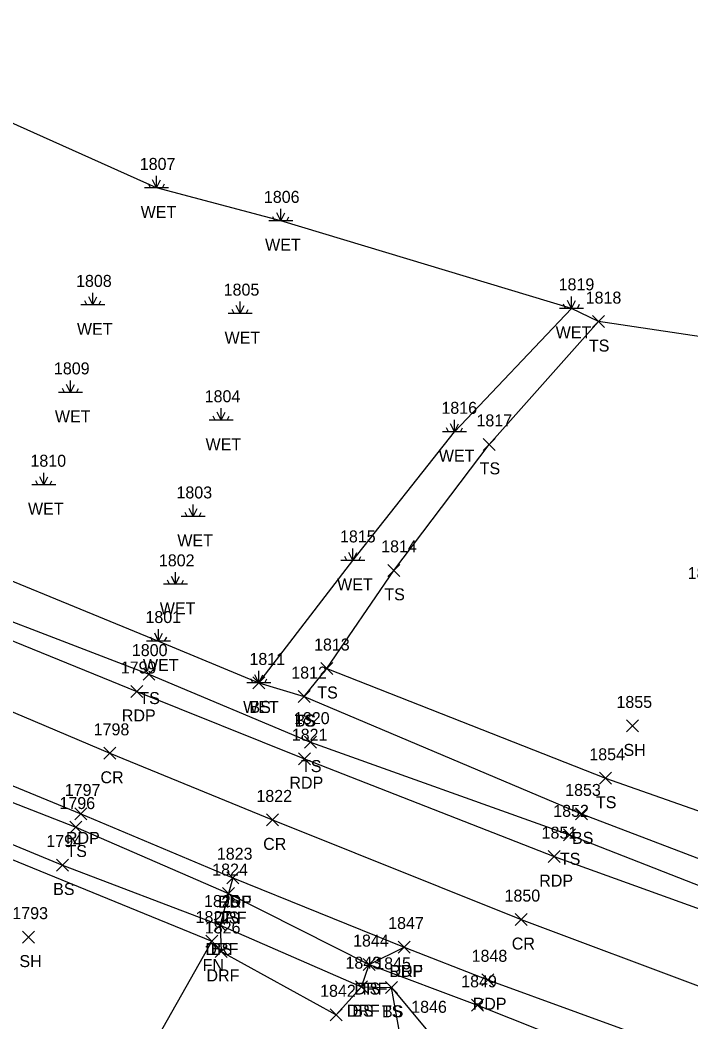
# Model space of a CAD drawing. Extents: x 1459992 to 1461532, y 647785 to 648535.
# Drawn here: x 1461005.9 to 1461117.9, y 648288.6 to 648455.8 of the extents above; entities that cross this region are included whole.
import ezdxf

# ---------------------------------------------------------------- set-up
doc = ezdxf.new("R2010")
doc.units = 0
for name, color, linetype in [('L_A', 7, 'Continuous'), ('L_I', 7, 'Continuous'), ('L_TIC', 7, 'Continuous'), ('LELB', 7, 'Continuous'), ('LFNC', 7, 'Continuous'), ('LSOGP', 7, 'Continuous'), ('LWET', 7, 'Continuous'), ('P_A', 7, 'Continuous'), ('P_I', 7, 'Continuous'), ('P_TIC', 7, 'Continuous'), ('PET', 7, 'Continuous'), ('PRC', 7, 'Continuous'), ('R_A', 7, 'Continuous'), ('R_I', 7, 'Continuous'), ('R_TIC', 7, 'Continuous'), ('RDF', 7, 'Continuous')]:
    doc.layers.add(name, color=color, linetype=linetype)

msp = doc.modelspace()

# ---------------------------------------------------------------- linework, layer by layer
at = {"layer": 'L_TIC'}
for points in [[(1461101.42, 648404.45), (1461103.42, 648406.45)], [(1461103.42, 648404.45), (1461101.42, 648406.45)], [(1461083.2, 648383.96), (1461085.2, 648385.96)], [(1461085.2, 648383.96), (1461083.2, 648385.96)], [(1461067.29, 648362.94), (1461069.29, 648364.94)], [(1461069.29, 648362.94), (1461067.29, 648364.94)], [(1461056.1, 648346.56), (1461058.1, 648348.56)], [(1461058.1, 648346.56), (1461056.1, 648348.56)], [(1461056.1, 648346.56), (1461058.1, 648348.56)], [(1461058.1, 648346.56), (1461056.1, 648348.56)], [(1461026.43, 648345.63), (1461028.43, 648347.63)], [(1461028.43, 648345.63), (1461026.43, 648347.63)], [(1461044.75, 648344.16), (1461046.75, 648346.16)], [(1461046.75, 648344.16), (1461044.75, 648346.16)], [(1461052.3, 648341.88), (1461054.3, 648343.88)], [(1461054.3, 648341.88), (1461052.3, 648343.88)], [(1461052.3, 648341.88), (1461054.3, 648343.88)], [(1461054.3, 648341.88), (1461052.3, 648343.88)], [(1461107.11, 648336.98), (1461109.11, 648338.98)], [(1461109.11, 648336.98), (1461107.11, 648338.98)], [(1461053.39, 648334.28), (1461055.39, 648336.28)], [(1461055.39, 648334.28), (1461053.39, 648336.28)], [(1461102.6, 648328.25), (1461104.6, 648330.25)], [(1461104.6, 648328.25), (1461102.6, 648330.25)], [(1461098.57, 648322.3), (1461100.57, 648324.3)], [(1461100.57, 648322.3), (1461098.57, 648324.3)], [(1461014.24, 648320.11), (1461016.24, 648322.11)], [(1461016.24, 648320.11), (1461014.24, 648322.11)], [(1461096.58, 648318.81), (1461098.58, 648320.81)], [(1461098.58, 648318.81), (1461096.58, 648320.81)], [(1461012, 648313.77), (1461014, 648315.77)], [(1461014, 648313.77), (1461012, 648315.77)], [(1461039.67, 648309.01), (1461041.67, 648311.01)], [(1461041.67, 648309.01), (1461039.67, 648311.01)], [(1461038.31, 648303.76), (1461040.31, 648305.76)], [(1461040.31, 648303.76), (1461038.31, 648305.76)], [(1461006.32, 648301.74), (1461008.32, 648303.74)], [(1461008.32, 648301.74), (1461006.32, 648303.74)], [(1461036.89, 648301.09), (1461038.89, 648303.09)], [(1461038.89, 648301.09), (1461036.89, 648303.09)], [(1461063.18, 648297.16), (1461065.18, 648299.16)], [(1461065.18, 648297.16), (1461063.18, 648299.16)], [(1461061.9, 648293.47), (1461063.9, 648295.47)], [(1461063.9, 648293.47), (1461061.9, 648295.47)], [(1461066.87, 648293.36), (1461068.87, 648295.36)], [(1461068.87, 648293.36), (1461066.87, 648295.36)], [(1461066.87, 648293.36), (1461068.87, 648295.36)], [(1461068.87, 648293.36), (1461066.87, 648295.36)], [(1461081.22, 648290.36), (1461083.22, 648292.36)], [(1461083.22, 648290.36), (1461081.22, 648292.36)]]:
    msp.add_lwpolyline(points, dxfattribs=at)
at = {"layer": 'LELB'}
for points in [[(1461053.3, 648342.88), (1461057.1, 648347.56), (1461103.6, 648329.25), (1461132.09, 648319.28), (1461156.26, 648311.83), (1461179.8, 648313.29), (1461203.15, 648318.77), (1461223.06, 648334.41), (1461252.96, 648329.42), (1461275.76, 648346.01), (1461293.92, 648360.57), (1461297.9, 648376.52), (1461309.92, 648382.32), (1461323.28, 648384.14), (1461344.65, 648406.6), (1461362.09, 648421.03), (1461389.72, 648443.02), (1461411.96, 648455.77)], [(1461045.75, 648345.16), (1461053.3, 648342.88), (1461099.57, 648323.3), (1461128.93, 648312.14), (1461154.02, 648304.18), (1461179.99, 648301.37), (1461204.48, 648303), (1461231.37, 648312.49), (1461255.41, 648321.87), (1461278.91, 648340.15), (1461298.64, 648355.28), (1461307.84, 648362.71), (1461328.64, 648380.09), (1461350.69, 648401.06), (1461366.77, 648414.15), (1461392.6, 648435.99), (1461415.7, 648449.6)], [(1460952.34, 648377.13), (1460985.69, 648362.66), (1461027.43, 648346.63), (1461054.39, 648335.28), (1461097.58, 648319.81), (1461127.3, 648308.18), (1461153.51, 648301.33), (1461179.78, 648297.83), (1461204.84, 648300.47), (1461233.15, 648308.09), (1461257.01, 648318.59), (1461281.51, 648336.52), (1461300.79, 648352.57), (1461310.07, 648360.68), (1461331.77, 648379.2), (1461352.47, 648399.38), (1461367.35, 648413.21), (1461394.44, 648433.89), (1461417.38, 648445.8)], [(1461057.1, 648347.56), (1461068.29, 648363.94), (1461084.2, 648384.96), (1461102.42, 648405.45)], [(1460941.15, 648349.78), (1460973.92, 648337.2), (1461015.24, 648321.11), (1461040.67, 648310.01), (1461064.18, 648298.16), (1461082.22, 648291.36), (1461125.02, 648274.34), (1461150.75, 648265.39), (1461172.28, 648256.95), (1461198.57, 648246.42), (1461223, 648236.28), (1461241.79, 648231.37), (1461257.62, 648226.89), (1461266.9, 648221.63), (1461276.01, 648214.68), (1461281.47, 648211.06), (1461286.34, 648210.46)], [(1460939.64, 648344.38), (1460971.19, 648332.05), (1461013, 648314.77), (1461039.31, 648304.76), (1461062.9, 648294.47), (1461067.87, 648294.36), (1461073.92, 648287.11), (1461122.33, 648270.19), (1461146.57, 648259.51), (1461168.44, 648252.02), (1461196.41, 648241.56), (1461220.18, 648231.28), (1461239.03, 648226.47), (1461251, 648216.36), (1461259.3, 648208.22), (1461262.9, 648204.94)], [(1461027.01, 648215.7), (1461045.55, 648230.6), (1461059.33, 648245.65), (1461068.32, 648268.11), (1461070.7, 648278.87), (1461067.87, 648294.36)]]:
    msp.add_lwpolyline(points, dxfattribs=at)
at = {"layer": 'LFNC'}
msp.add_lwpolyline([(1460991.77, 648320.92), (1461037.89, 648302.09), (1461026.11, 648281.23)], dxfattribs=at)
at = {"layer": 'LSOGP'}
msp.add_lwpolyline([(1461138.91, 648400.04), (1461102.42, 648405.45), (1461097.92, 648407.66), (1461049.42, 648422.26), (1461028.66, 648427.76), (1461000.6, 648440.35), (1460993.65, 648440.24), (1460983.9, 648441.23), (1460975.78, 648424.57), (1460965.77, 648408.07), (1460958.96, 648389.21), (1460957.54, 648386.1), (1460955.38, 648382.22), (1460952.34, 648377.13), (1460950.93, 648374.58), (1460946.83, 648364.55), (1460942.85, 648353.98), (1460941.15, 648349.78), (1460940.52, 648347.48), (1460939.64, 648344.38), (1460937.03, 648338.08), (1460933.59, 648326.77), (1460928.43, 648303.96), (1460921.84, 648282.44)], dxfattribs=at)
at = {"layer": 'LWET'}
for p, q in [((1461028.66, 648427.76), (1461028.66, 648429.76)), ((1461027.66, 648427.76), (1461027.33, 648428.43)), ((1461028.66, 648427.76), (1461028, 648429.1)), ((1461028.66, 648427.76), (1461029.33, 648429.1)), ((1461029.66, 648427.76), (1461030, 648428.43)), ((1461030.66, 648427.76), (1461026.66, 648427.76)), ((1461048.42, 648422.26), (1461048.09, 648422.93)), ((1461049.42, 648422.26), (1461048.76, 648423.6)), ((1461049.42, 648422.26), (1461049.42, 648424.26)), ((1461049.42, 648422.26), (1461050.09, 648423.6)), ((1461050.42, 648422.26), (1461050.76, 648422.93)), ((1461051.42, 648422.26), (1461047.42, 648422.26)), ((1461018.04, 648408.24), (1461017.37, 648409.58)), ((1461018.04, 648408.24), (1461018.04, 648410.24)), ((1461018.04, 648408.24), (1461018.7, 648409.58)), ((1461097.92, 648407.66), (1461097.92, 648409.66)), ((1461020.04, 648408.24), (1461016.04, 648408.24)), ((1461017.04, 648408.24), (1461016.7, 648408.91)), ((1461019.04, 648408.24), (1461019.37, 648408.91)), ((1461042.66, 648406.78), (1461042, 648408.12)), ((1461042.66, 648406.78), (1461042.66, 648408.78)), ((1461042.66, 648406.78), (1461043.33, 648408.12)), ((1461096.92, 648407.66), (1461096.58, 648408.33)), ((1461097.92, 648407.66), (1461097.25, 648408.99)), ((1461097.92, 648407.66), (1461098.58, 648408.99)), ((1461098.92, 648407.66), (1461099.25, 648408.33)), ((1461044.66, 648406.78), (1461040.66, 648406.78)), ((1461041.66, 648406.78), (1461041.33, 648407.45)), ((1461043.66, 648406.78), (1461044, 648407.45)), ((1461099.92, 648407.66), (1461095.92, 648407.66)), ((1461014.35, 648393.64), (1461013.68, 648394.97)), ((1461014.35, 648393.64), (1461014.35, 648395.64)), ((1461014.35, 648393.64), (1461015.02, 648394.97)), ((1461016.35, 648393.64), (1461012.35, 648393.64)), ((1461013.35, 648393.64), (1461013.02, 648394.3)), ((1461015.35, 648393.64), (1461015.68, 648394.3)), ((1461038.49, 648388.99), (1461038.16, 648389.66)), ((1461039.49, 648388.99), (1461038.83, 648390.32)), ((1461039.49, 648388.99), (1461039.49, 648390.99)), ((1461039.49, 648388.99), (1461040.16, 648390.32)), ((1461040.49, 648388.99), (1461040.83, 648389.66)), ((1461041.49, 648388.99), (1461037.49, 648388.99)), ((1461078.4, 648387.06), (1461077.73, 648388.4)), ((1461078.4, 648387.06), (1461078.4, 648389.06)), ((1461078.4, 648387.06), (1461079.07, 648388.4)), ((1461080.4, 648387.06), (1461076.4, 648387.06)), ((1461077.4, 648387.06), (1461077.07, 648387.73)), ((1461079.4, 648387.06), (1461079.73, 648387.73)), ((1461009.86, 648378.23), (1461009.19, 648379.56)), ((1461009.86, 648378.23), (1461009.86, 648380.23)), ((1461009.86, 648378.23), (1461010.53, 648379.56)), ((1461011.86, 648378.23), (1461007.86, 648378.23)), ((1461008.86, 648378.23), (1461008.53, 648378.9)), ((1461010.86, 648378.23), (1461011.19, 648378.9)), ((1461034.78, 648372.94), (1461034.78, 648374.94)), ((1461036.78, 648372.94), (1461032.78, 648372.94)), ((1461033.78, 648372.94), (1461033.45, 648373.61)), ((1461034.78, 648372.94), (1461034.11, 648374.28)), ((1461034.78, 648372.94), (1461035.45, 648374.28)), ((1461035.78, 648372.94), (1461036.11, 648373.61)), ((1461060.43, 648365.6), (1461060.1, 648366.27)), ((1461061.43, 648365.6), (1461060.76, 648366.94)), ((1461061.43, 648365.6), (1461061.43, 648367.6)), ((1461061.43, 648365.6), (1461062.1, 648366.94)), ((1461062.43, 648365.6), (1461062.76, 648366.27)), ((1461063.43, 648365.6), (1461059.43, 648365.6)), ((1461031.85, 648361.61), (1461031.19, 648362.94)), ((1461031.85, 648361.61), (1461031.85, 648363.61)), ((1461031.85, 648361.61), (1461032.52, 648362.94)), ((1461033.85, 648361.61), (1461029.85, 648361.61)), ((1461030.85, 648361.61), (1461030.52, 648362.28)), ((1461032.85, 648361.61), (1461033.19, 648362.28)), ((1461028.04, 648352.15), (1461027.71, 648352.81)), ((1461029.04, 648352.15), (1461028.38, 648353.48)), ((1461029.04, 648352.15), (1461029.04, 648354.15)), ((1461029.04, 648352.15), (1461029.71, 648353.48)), ((1461030.04, 648352.15), (1461030.38, 648352.81)), ((1461031.04, 648352.15), (1461027.04, 648352.15)), ((1461045.75, 648345.16), (1461045.09, 648346.49)), ((1461045.75, 648345.16), (1461045.75, 648347.16)), ((1461045.75, 648345.16), (1461046.42, 648346.49)), ((1461047.75, 648345.16), (1461043.75, 648345.16)), ((1461044.75, 648345.16), (1461044.42, 648345.83)), ((1461046.75, 648345.16), (1461047.09, 648345.83))]:
    msp.add_line(p, q, dxfattribs=at)
msp.add_lwpolyline([(1460955.38, 648382.22), (1460970.16, 648376.13), (1460988.62, 648368.71), (1461029.04, 648352.15), (1461045.75, 648345.16), (1461061.43, 648365.6), (1461078.4, 648387.06), (1461097.92, 648407.66)], dxfattribs=at)
at = {"layer": 'P_TIC'}
for points in [[(1461024.42, 648342.73), (1461026.42, 648344.73)], [(1461026.42, 648342.73), (1461024.42, 648344.73)], [(1461019.89, 648332.41), (1461021.89, 648334.41)], [(1461021.89, 648332.41), (1461019.89, 648334.41)], [(1461052.38, 648331.51), (1461054.38, 648333.51)], [(1461054.38, 648331.51), (1461052.38, 648333.51)], [(1461015.08, 648322.29), (1461017.08, 648324.29)], [(1461017.08, 648322.29), (1461015.08, 648324.29)], [(1461047.05, 648321.3), (1461049.05, 648323.3)], [(1461049.05, 648321.3), (1461047.05, 648323.3)], [(1461094.05, 648315.17), (1461096.05, 648317.17)], [(1461096.05, 648315.17), (1461094.05, 648317.17)], [(1461040.44, 648311.66), (1461042.44, 648313.66)], [(1461042.44, 648311.66), (1461040.44, 648313.66)], [(1461088.53, 648304.67), (1461090.53, 648306.67)], [(1461090.53, 648304.67), (1461088.53, 648306.67)], [(1461069.03, 648300.09), (1461071.03, 648302.09)], [(1461071.03, 648300.09), (1461069.03, 648302.09)], [(1461082.95, 648294.62), (1461084.95, 648296.62)], [(1461084.95, 648294.62), (1461082.95, 648296.62)]]:
    msp.add_lwpolyline(points, dxfattribs=at)
at = {"layer": 'PET'}
for points in [[(1460950.93, 648374.58), (1460984.69, 648360.32), (1461025.42, 648343.73), (1461053.38, 648332.51), (1461095.05, 648316.17), (1461126.17, 648304.95), (1461152.62, 648298.48), (1461179.86, 648295.54), (1461205.35, 648297.28), (1461234.43, 648304.94), (1461258.07, 648315.7), (1461283.68, 648333.5), (1461302.87, 648349.75), (1461333.02, 648377.55), (1461355.02, 648397.13), (1461371.06, 648410.57), (1461396.62, 648429.43), (1461418.97, 648443.38)], [(1460942.85, 648353.98), (1460975.34, 648340.07), (1461016.08, 648323.29), (1461041.44, 648312.66), (1461070.03, 648301.09), (1461083.95, 648295.62), (1461128.85, 648279.26), (1461164.21, 648269.58), (1461178.63, 648262.65), (1461203.09, 648251.99), (1461227.86, 648243.02), (1461244.86, 648238.13), (1461258.8, 648233.38), (1461270.23, 648226.19), (1461279.65, 648219.62), (1461287.61, 648211.81)]]:
    msp.add_lwpolyline(points, dxfattribs=at)
at = {"layer": 'PRC'}
msp.add_lwpolyline([(1460946.83, 648364.55), (1460979.81, 648350.87), (1461020.89, 648333.41), (1461048.05, 648322.3), (1461089.53, 648305.67), (1461120.42, 648294.12), (1461149.17, 648286), (1461180.56, 648282.29), (1461207.18, 648283.7), (1461238.84, 648291.79), (1461263.78, 648303.51), (1461290.77, 648322.92), (1461310.31, 648340.94), (1461342.22, 648370.37), (1461365.17, 648390.4), (1461371.57, 648396.04), (1461402.62, 648419.98), (1461424.86, 648433.53)], dxfattribs=at)
at = {"layer": 'R_TIC'}
for points in [[(1461040.44, 648311.66), (1461042.44, 648313.66)], [(1461042.44, 648311.66), (1461040.44, 648313.66)], [(1461039.67, 648309.01), (1461041.67, 648311.01)], [(1461041.67, 648309.01), (1461039.67, 648311.01)], [(1461038.31, 648303.76), (1461040.31, 648305.76)], [(1461040.31, 648303.76), (1461038.31, 648305.76)], [(1461038.48, 648299.35), (1461040.48, 648301.35)], [(1461040.48, 648299.35), (1461038.48, 648301.35)], [(1461069.03, 648300.09), (1461071.03, 648302.09)], [(1461071.03, 648300.09), (1461069.03, 648302.09)], [(1461063.18, 648297.16), (1461065.18, 648299.16)], [(1461065.18, 648297.16), (1461063.18, 648299.16)], [(1461061.9, 648293.47), (1461063.9, 648295.47)], [(1461063.9, 648293.47), (1461061.9, 648295.47)], [(1461057.68, 648288.78), (1461059.68, 648290.78)], [(1461059.68, 648288.78), (1461057.68, 648290.78)]]:
    msp.add_lwpolyline(points, dxfattribs=at)
at = {"layer": 'RDF'}
msp.add_lwpolyline([(1461041.44, 648312.66), (1461040.67, 648310.01), (1461039.31, 648304.76), (1461039.48, 648300.35), (1461058.68, 648289.78), (1461062.9, 648294.47), (1461064.18, 648298.16), (1461070.03, 648301.09)], dxfattribs=at)

# ---------------------------------------------------------------- texts
at = {"layer": 'L_A'}
for s, p in [('WET', (1461026.04, 648422.76)), ('WET', (1461046.8, 648417.26)), ('WET', (1461015.41, 648403.24)), ('WET', (1461095.29, 648402.66)), ('WET', (1461040.04, 648401.78)), ('TS', (1461100.83, 648400.45)), ('WET', (1461011.73, 648388.64)), ('WET', (1461036.87, 648383.99)), ('WET', (1461075.78, 648382.06)), ('TS', (1461082.61, 648379.96)), ('WET', (1461007.24, 648373.23)), ('WET', (1461032.16, 648367.94)), ('WET', (1461058.81, 648360.6)), ('TS', (1461066.7, 648358.94)), ('WET', (1461029.23, 648356.61)), ('WET', (1461026.42, 648347.15)), ('TS', (1461055.51, 648342.56)), ('TS', (1461055.51, 648342.56)), ('TS', (1461025.83, 648341.63)), ('WET', (1461043.13, 648340.16)), ('BS', (1461044.19, 648340.16)), ('TS', (1461051.71, 648337.88)), ('BS', (1461051.74, 648337.88)), ('SH', (1461106.6, 648332.98)), ('TS', (1461052.8, 648330.28)), ('TS', (1461102, 648324.25)), ('BS', (1461098.01, 648318.3)), ('TS', (1461013.65, 648316.11)), ('TS', (1461095.99, 648314.81)), ('BS', (1461011.44, 648309.77)), ('TS', (1461039.08, 648305.01)), ('BS', (1461037.75, 648299.76)), ('SH', (1461005.81, 648297.74)), ('FN', (1461036.37, 648297.09)), ('TS', (1461062.59, 648293.16)), ('BS', (1461061.34, 648289.47)), ('TS', (1461066.28, 648289.36)), ('BS', (1461066.31, 648289.36))]:
    msp.add_text(s, height=2, dxfattribs=at).set_placement(p)
at = {"layer": 'L_I'}
for s, p in [('1807', (1461025.89, 648430.76)), ('1806', (1461046.6, 648425.26)), ('1808', (1461015.26, 648411.24)), ('1805', (1461039.89, 648409.78)), ('1819', (1461095.78, 648410.66)), ('1818', (1461100.29, 648408.45)), ('1809', (1461011.57, 648396.64)), ('1804', (1461036.72, 648391.99)), ('1816', (1461076.22, 648390.06)), ('1817', (1461082.07, 648387.96)), ('1810', (1461007.65, 648381.23)), ('1803', (1461032.01, 648375.94)), ('1815', (1461059.3, 648368.6)), ('1814', (1461066.17, 648366.94)), ('1802', (1461029.08, 648364.61)), ('1856', (1461117.31, 648362.48)), ('1801', (1461026.84, 648355.15)), ('1800', (1461024.57, 648349.63)), ('1813', (1461054.97, 648350.56)), ('1813', (1461054.97, 648350.56)), ('1811', (1461044.19, 648348.16)), ('1811', (1461044.19, 648348.16)), ('1812', (1461051.17, 648345.88)), ('1812', (1461051.17, 648345.88)), ('1855', (1461105.42, 648340.98)), ('1820', (1461051.62, 648338.28)), ('1854', (1461100.9, 648332.25)), ('1853', (1461096.87, 648326.3)), ('1796', (1461012.49, 648324.11)), ('1852', (1461094.88, 648322.81)), ('1794', (1461010.3, 648317.77)), ('1824', (1461037.98, 648313.01)), ('1825', (1461036.61, 648307.76)), ('1793', (1461004.63, 648305.74)), ('1827', (1461035.2, 648305.09)), ('1844', (1461061.48, 648301.16)), ('1843', (1461060.21, 648297.47)), ('1845', (1461065.18, 648297.36)), ('1845', (1461065.18, 648297.36)), ('1849', (1461079.52, 648294.36)), ('1846', (1461071.18, 648290.11)), ('1846', (1461071.18, 648290.11))]:
    msp.add_text(s, height=2, dxfattribs=at).set_placement(p)
at = {"layer": 'P_A'}
for s, p in [('RDP', (1461022.9, 648338.73)), ('CR', (1461019.33, 648328.41)), ('RDP', (1461050.86, 648327.51)), ('RDP', (1461013.57, 648318.29)), ('CR', (1461046.48, 648317.3)), ('RDP', (1461092.54, 648311.17)), ('RDP', (1461038.93, 648307.66)), ('CR', (1461087.96, 648300.67)), ('RDP', (1461067.52, 648296.09)), ('RDP', (1461081.44, 648290.62))]:
    msp.add_text(s, height=2, dxfattribs=at).set_placement(p)
at = {"layer": 'P_I'}
for s, p in [('1799', (1461022.72, 648346.73)), ('1798', (1461018.2, 648336.41)), ('1821', (1461051.25, 648335.51)), ('1797', (1461013.38, 648326.29)), ('1822', (1461045.35, 648325.3)), ('1851', (1461092.93, 648319.17)), ('1823', (1461038.75, 648315.66)), ('1850', (1461086.75, 648308.67)), ('1847', (1461067.34, 648304.09)), ('1848', (1461081.26, 648298.62))]:
    msp.add_text(s, height=2, dxfattribs=at).set_placement(p)
at = {"layer": 'R_A'}
for p in [(1461038.98, 648307.66), (1461038.21, 648305.01), (1461036.84, 648299.76), (1461067.57, 648296.09), (1461037.02, 648295.35), (1461061.71, 648293.16), (1461060.44, 648289.47)]:
    msp.add_text('DRF', height=2, dxfattribs=at).set_placement(p)
at = {"layer": 'R_I'}
for s, p in [('1823', (1461038.75, 648315.66)), ('1824', (1461037.98, 648313.01)), ('1825', (1461036.61, 648307.76)), ('1847', (1461067.34, 648304.09)), ('1826', (1461036.74, 648303.35)), ('1844', (1461061.48, 648301.16)), ('1843', (1461060.21, 648297.47)), ('1842', (1461055.98, 648292.78))]:
    msp.add_text(s, height=2, dxfattribs=at).set_placement(p)

doc.saveas('drawing.dxf')
